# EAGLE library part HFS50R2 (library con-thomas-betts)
THOMAS&BETTS
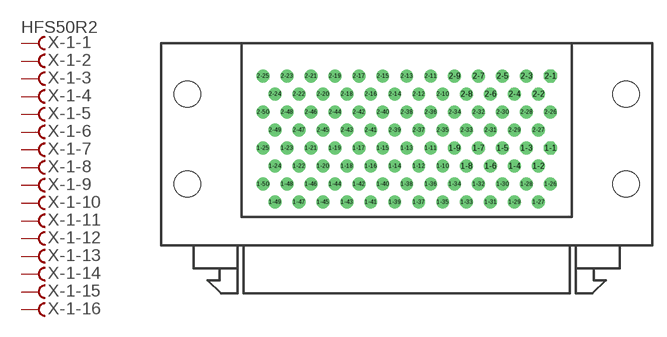
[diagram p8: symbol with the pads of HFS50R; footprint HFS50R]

Designator prefix X; gates -1-1=FV -1-2=F -1-3=F -1-4=F -1-5=F -1-6=F -1-7=F -1-8=F -1-9=F -1-10=F -1-11=F -1-12=F -1-13=F -1-14=F -1-15=F -1-16=F -1-17=F -1-18=F -1-19=F -1-20=F -1-21=F -1-22=F -1-23=F -1-24=F -1-25=F -1-26=F -1-27=F -1-28=F -1-29=F -1-30=F -1-31=F -1-32=F -1-33=F -1-34=F -1-35=F -1-36=F -1-37=F -1-38=F -1-39=F -1-40=F -1-41=F -1-42=F -1-43=F -1-44=F -1-45=F -1-46=F -1-47=F -1-48=F -1-49=F -1-50=F -2-1=FV -2-2=F -2-3=F -2-4=F -2-5=F -2-6=F -2-7=F -2-8=F -2-9=F -2-10=F -2-11=F -2-12=F -2-13=F -2-14=F -2-15=F -2-16=F -2-17=F -2-18=F -2-19=F -2-20=F -2-21=F -2-22=F -2-23=F -2-24=F -2-25=F -2-26=F -2-27=F -2-28=F -2-29=F -2-30=F -2-31=F -2-32=F -2-33=F -2-34=F -2-35=F -2-36=F -2-37=F -2-38=F -2-39=F -2-40=F -2-41=F -2-42=F -2-43=F -2-44=F -2-45=F -2-46=F -2-47=F -2-48=F -2-49=F -2-50=F

## HFS50R2 (OC_FARNELL: unknown; OC_NEWARK: unknown)  [HFS50R]
1-1  -1-1:F  pas
1-2  -1-2:F  pas
1-3  -1-3:F  pas
1-4  -1-4:F  pas
1-5  -1-5:F  pas
1-6  -1-6:F  pas
1-7  -1-7:F  pas
1-8  -1-8:F  pas
1-9  -1-9:F  pas
1-10  -1-10:F  pas
1-11  -1-11:F  pas
1-12  -1-12:F  pas
1-13  -1-13:F  pas
1-14  -1-14:F  pas
1-15  -1-15:F  pas
1-16  -1-16:F  pas
1-17  -1-17:F  pas
1-18  -1-18:F  pas
1-19  -1-19:F  pas
1-20  -1-20:F  pas
1-21  -1-21:F  pas
1-22  -1-22:F  pas
1-23  -1-23:F  pas
1-24  -1-24:F  pas
1-25  -1-25:F  pas
1-26  -1-26:F  pas
1-27  -1-27:F  pas
1-28  -1-28:F  pas
1-29  -1-29:F  pas
1-30  -1-30:F  pas
1-31  -1-31:F  pas
1-32  -1-32:F  pas
1-33  -1-33:F  pas
1-34  -1-34:F  pas
1-35  -1-35:F  pas
1-36  -1-36:F  pas
1-37  -1-37:F  pas
1-38  -1-38:F  pas
1-39  -1-39:F  pas
1-40  -1-40:F  pas
1-41  -1-41:F  pas
1-42  -1-42:F  pas
1-43  -1-43:F  pas
1-44  -1-44:F  pas
1-45  -1-45:F  pas
1-46  -1-46:F  pas
1-47  -1-47:F  pas
1-48  -1-48:F  pas
1-49  -1-49:F  pas
1-50  -1-50:F  pas
2-1  -2-1:F  pas
2-2  -2-2:F  pas
2-3  -2-3:F  pas
2-4  -2-4:F  pas
2-5  -2-5:F  pas
2-6  -2-6:F  pas
2-7  -2-7:F  pas
2-8  -2-8:F  pas
2-9  -2-9:F  pas
2-10  -2-10:F  pas
2-11  -2-11:F  pas
2-12  -2-12:F  pas
2-13  -2-13:F  pas
2-14  -2-14:F  pas
2-15  -2-15:F  pas
2-16  -2-16:F  pas
2-17  -2-17:F  pas
2-18  -2-18:F  pas
2-19  -2-19:F  pas
2-20  -2-20:F  pas
2-21  -2-21:F  pas
2-22  -2-22:F  pas
2-23  -2-23:F  pas
2-24  -2-24:F  pas
2-25  -2-25:F  pas
2-26  -2-26:F  pas
2-27  -2-27:F  pas
2-28  -2-28:F  pas
2-29  -2-29:F  pas
2-30  -2-30:F  pas
2-31  -2-31:F  pas
2-32  -2-32:F  pas
2-33  -2-33:F  pas
2-34  -2-34:F  pas
2-35  -2-35:F  pas
2-36  -2-36:F  pas
2-37  -2-37:F  pas
2-38  -2-38:F  pas
2-39  -2-39:F  pas
2-40  -2-40:F  pas
2-41  -2-41:F  pas
2-42  -2-42:F  pas
2-43  -2-43:F  pas
2-44  -2-44:F  pas
2-45  -2-45:F  pas
2-46  -2-46:F  pas
2-47  -2-47:F  pas
2-48  -2-48:F  pas
2-49  -2-49:F  pas
2-50  -2-50:F  pas

## Footprint HFS50R (pad centres in mm)
THOMAS&BETTS Fine Pitch "D" Connector HFS50Rx29x
drill 0.864 octagon: 1-1 15.24,8.87; 2-1 15.24,16.51
drill 0.864 round: 1-2 13.97,6.96; 1-3 12.7,8.87; 1-4 11.43,6.96; 1-5 10.16,8.87; 1-6 8.89,6.96; 1-7 7.62,8.87; 1-8 6.35,6.96; 1-9 5.08,8.87; 1-10 3.81,6.96; 1-11 2.54,8.87; 1-12 1.27,6.96; 1-13 0,8.87; 1-14 -1.27,6.96; 1-15 -2.54,8.87; 1-16 -3.81,6.96; 1-17 -5.08,8.87; 1-18 -6.35,6.96; 1-19 -7.62,8.87; 1-20 -8.89,6.96; 1-21 -10.16,8.87; 1-22 -11.43,6.96; 1-23 -12.7,8.87; 1-24 -13.97,6.96; 1-25 -15.24,8.87; 1-26 15.24,5.05; 1-27 13.97,3.14; 1-28 12.7,5.05; 1-29 11.43,3.14; 1-30 10.16,5.05; 1-31 8.89,3.14; 1-32 7.62,5.05; 1-33 6.35,3.14; 1-34 5.08,5.05; 1-35 3.81,3.14; 1-36 2.54,5.05; 1-37 1.27,3.14; 1-38 0,5.05; 1-39 -1.27,3.14; 1-40 -2.54,5.05; 1-41 -3.81,3.14; 1-42 -5.08,5.05; 1-43 -6.35,3.14; 1-44 -7.62,5.05; 1-45 -8.89,3.14; 1-46 -10.16,5.05; 1-47 -11.43,3.14; 1-48 -12.7,5.05; 1-49 -13.97,3.14; 1-50 -15.24,5.05; 2-2 13.97,14.6; 2-3 12.7,16.51; 2-4 11.43,14.6; 2-5 10.16,16.51; 2-6 8.89,14.6; 2-7 7.62,16.51; 2-8 6.35,14.6; 2-9 5.08,16.51; 2-10 3.81,14.6; 2-11 2.54,16.51; 2-12 1.27,14.6; 2-13 0,16.51; 2-14 -1.27,14.6; 2-15 -2.54,16.51; 2-16 -3.81,14.6; 2-17 -5.08,16.51; 2-18 -6.35,14.6; 2-19 -7.62,16.51; 2-20 -8.89,14.6; 2-21 -10.16,16.51; 2-22 -11.43,14.6; 2-23 -12.7,16.51; 2-24 -13.97,14.6; 2-25 -15.24,16.51; 2-26 15.24,12.69; 2-27 13.97,10.78; 2-28 12.7,12.69; 2-29 11.43,10.78; 2-30 10.16,12.69; 2-31 8.89,10.78; 2-32 7.62,12.69; 2-33 6.35,10.78; 2-34 5.08,12.69; 2-35 3.81,10.78; 2-36 2.54,12.69; 2-37 1.27,10.78; 2-38 0,12.69; 2-39 -1.27,10.78; 2-40 -2.54,12.69; 2-41 -3.81,10.78; 2-42 -5.08,12.69; 2-43 -6.35,10.78; 2-44 -7.62,12.69; 2-45 -8.89,10.78; 2-46 -10.16,12.69; 2-47 -11.43,10.78; 2-48 -12.7,12.69; 2-49 -13.97,10.78; 2-50 -15.24,12.69
hole 2.769 at 23.241,5.05
hole 2.769 at -23.241,5.05
hole 2.769 at 23.241,14.6
hole 2.769 at -23.241,14.6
